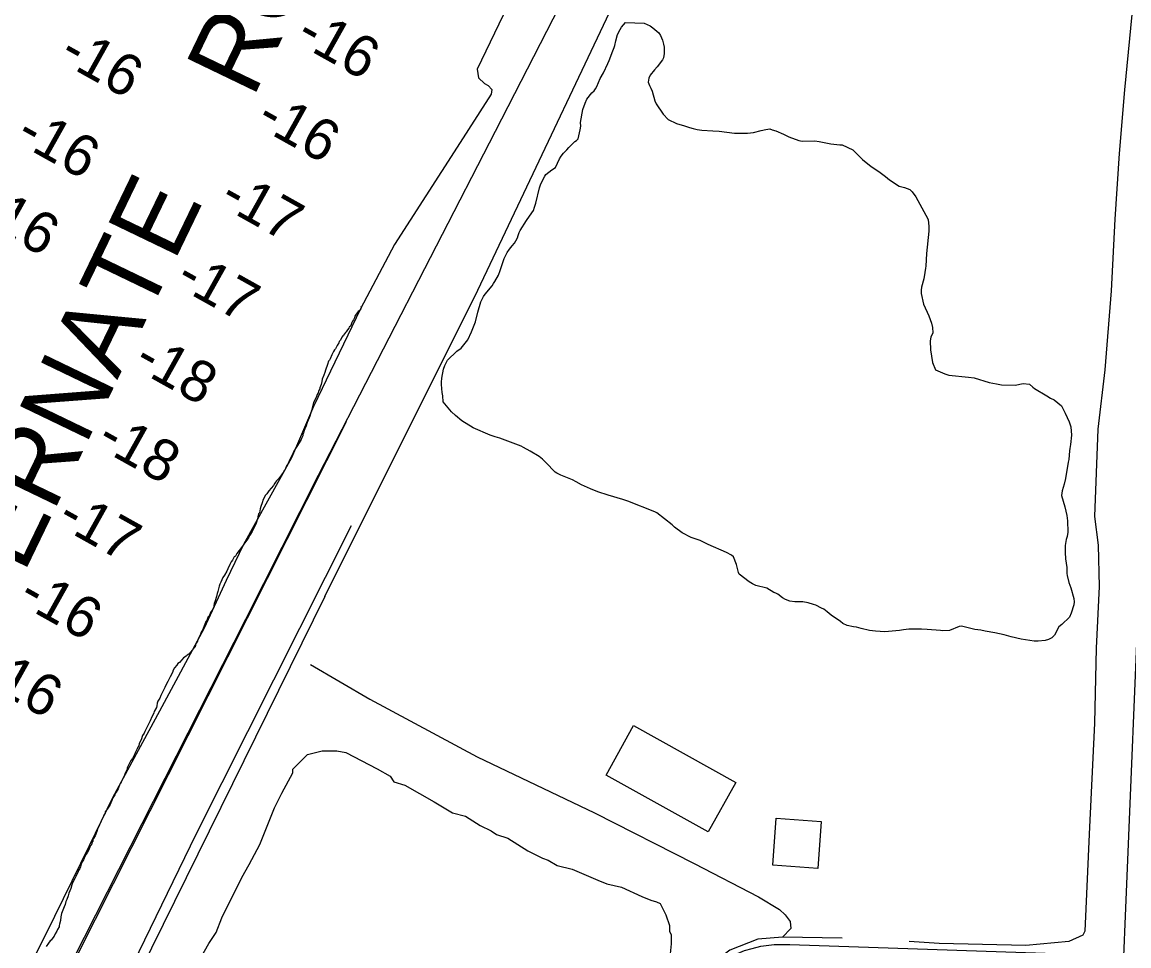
# Model space of a CAD drawing. Extents: x 3683402 to 3721514, y 487807 to 513565.
# Drawn here: x 3703895 to 3705098, y 507300 to 508305 of the extents above; entities that cross this region are included whole.
import ezdxf

# ---------------------------------------------------------------- set-up
doc = ezdxf.new("R2010")
doc.units = 0
for name, color, linetype in [('V-BLDG-OTLN', 7, 'Continuous'), ('V-LEVE-TOET', 7, 'Continuous'), ('V-RIVR-IDEN', 7, 'Continuous'), ('V-ROAD-CNTR', 7, 'Continuous'), ('V-SITE-VEGE', 7, 'Continuous'), ('V-TOPO-SHOR', 7, 'Continuous'), ('V-TOPO-SPOT', 7, 'Continuous')]:
    doc.layers.add(name, color=color, linetype=linetype)

msp = doc.modelspace()

# ---------------------------------------------------------------- linework, layer by layer
at = {"layer": 'V-BLDG-OTLN'}
for points in [[(3704670.7, 507478.2), (3704640.7, 507424.4), (3704529.6, 507486.3), (3704559.6, 507540.1)], [(3704714.4, 507439.4), (3704763.4, 507435.9), (3704759.7, 507384.6), (3704710.7, 507388.2)]]:
    msp.add_lwpolyline(points, close=True, dxfattribs=at)
at = {"layer": 'V-LEVE-TOET'}
for points in [[(3704223.9, 507680.3), (3704390.1, 508013.5), (3704576.9, 508407.5), (3704607.9, 508471.4), (3704662, 508586.2), (3704740, 508732.4), (3704803.2, 508853.8), (3704921.3, 509079.6), (3705040.6, 509320.9)], [(3704216.9, 507812.4), (3704409.6, 508186.4), (3704555.8, 508472.2), (3704578, 508525.2), (3704643.5, 508643), (3704779.8, 508906.1), (3704918.2, 509195.3), (3704970.6, 509304.3)], [(3703895.1, 507171.6), (3704054, 507487), (3704247.6, 507870.6)], [(3704223.9, 507680.3), (3703846.7, 506915.4), (3703528.7, 506294), (3703355.4, 505976.9), (3703338.6, 505959.3), (3703328.3, 505955.1), (3703313.5, 505956.1), (3703301.9, 505957.5), (3703294.3, 505960.5), (3703290.2, 505965.7), (3703290.1, 505978.7), (3703297.6, 506003.1), (3703397.2, 506210.1), (3703599.2, 506592.2), (3703887.4, 507161.4), (3704138.1, 507655.6), (3704216.9, 507812.4)], [(3703947.4, 507140.5), (3704084.3, 507421.8), (3704253, 507757.5)]]:
    msp.add_lwpolyline(points, dxfattribs=at)
at = {"layer": 'V-ROAD-CNTR'}
for points in [[(3705031.4, 505524.3), (3705055.3, 506203.7), (3705088.8, 507201.8), (3705115.9, 507856.6)], [(3703461.3, 506109.4), (3704007, 506082.8), (3704014.4, 506082.7), (3704018.5, 506082.7), (3704022, 506083.2), (3704027.1, 506085.1), (3704030.7, 506086.8), (3704033.9, 506089.4), (3704039, 506093.4), (3704044.7, 506097.7), (3704046.9, 506100), (3704050, 506103.8), (3704191.8, 506389.1), (3704638.4, 507256.7), (3704651.6, 507274.7), (3704660.9, 507285.1), (3704669.8, 507291), (3704680.1, 507295.4), (3704688.5, 507297.6), (3704697.8, 507300.3), (3704712.3, 507301.8), (3704729.2, 507301.8), (3705092.3, 507289.5)]]:
    msp.add_lwpolyline(points, dxfattribs=at)
at = {"layer": 'V-SITE-VEGE'}
for points in [[(3704584.8, 507771.4), (3704582.6, 507772.5), (3704553.3, 507784.2), (3704548, 507785.9), (3704531.9, 507790.5), (3704520.7, 507794.4), (3704512.7, 507797.5), (3704502.9, 507801.7), (3704497.1, 507805.2), (3704493, 507807.2), (3704480.5, 507812.5), (3704476.1, 507814.7), (3704474.3, 507815.8), (3704464, 507826.2), (3704460.6, 507829.7), (3704457, 507832.6), (3704447.2, 507838.6), (3704440, 507842.3), (3704437.3, 507843.8), (3704414.1, 507852.6), (3704409.2, 507853.9), (3704403.6, 507855.9), (3704385.1, 507863.8), (3704373, 507871.3), (3704366.1, 507877.3), (3704361.8, 507881.3), (3704359.8, 507883.5), (3704352.6, 507892.3), (3704352.1, 507898.6), (3704351.6, 507902.4), (3704350.9, 507910.8), (3704350.9, 507913.5), (3704351.3, 507918), (3704353, 507927.8), (3704354.4, 507931.8), (3704357.2, 507937.4), (3704367.4, 507947.2), (3704372.3, 507950.6), (3704379.4, 507959.6), (3704383.3, 507968.3), (3704387.7, 507979), (3704390.3, 507989.5), (3704393.4, 508000.9), (3704396.5, 508006.5), (3704398.2, 508009.2), (3704405.7, 508018.3), (3704407.3, 508020.8), (3704408.8, 508023), (3704412.8, 508029.7), (3704414.6, 508034.9), (3704417, 508042.7), (3704418.9, 508048.1), (3704422, 508054.5), (3704424.7, 508058.3), (3704427.5, 508061.9), (3704430.2, 508064.6), (3704431.7, 508067.3), (3704433.3, 508070.4), (3704434.2, 508072.9), (3704435, 508076.4), (3704436.1, 508078.5), (3704443, 508089.4), (3704446.5, 508094.1), (3704450.7, 508100.2), (3704452, 508104), (3704453.3, 508108.2), (3704457.2, 508124.9), (3704458.3, 508128.1), (3704461.2, 508134.1), (3704463, 508137.4), (3704464.3, 508139.5), (3704470.5, 508144.4), (3704474.7, 508147.1), (3704479.1, 508156.3), (3704480.9, 508159.4), (3704483.3, 508162.5), (3704487.1, 508166.1), (3704489.3, 508168.8), (3704495.5, 508175.1), (3704497.3, 508176.4), (3704499.3, 508178.2), (3704501.6, 508187.8), (3704502.1, 508191.8), (3704502, 508195.8), (3704504.2, 508209.9), (3704506.8, 508216.8), (3704508.8, 508221.3), (3704514.3, 508228.2), (3704516.8, 508230.5), (3704518.1, 508232.5), (3704519.4, 508235.2), (3704523.1, 508243.7), (3704526.7, 508249.9), (3704531.7, 508260), (3704532.8, 508263.3), (3704537, 508274), (3704538.5, 508277.4), (3704539.2, 508279.6), (3704540.3, 508284.8), (3704542.2, 508291.7), (3704544.9, 508297)], [(3704544.9, 508297), (3704546.4, 508299.5), (3704550.8, 508304.7), (3704571.1, 508304.1), (3704577.4, 508301), (3704580.5, 508299)], [(3704580.5, 508299), (3704587, 508293.5), (3704588.6, 508290.6), (3704590.8, 508285.3), (3704592.2, 508281.1), (3704592.7, 508277.9), (3704592.9, 508271), (3704592.1, 508266.4), (3704591, 508263.9), (3704585.2, 508256.3), (3704582.4, 508253.2), (3704577.7, 508247.3), (3704576.2, 508244.2), (3704575.3, 508239.7), (3704576.7, 508236), (3704578.2, 508233.3), (3704579.8, 508230), (3704582.6, 508219.3), (3704583.9, 508216.2), (3704591.6, 508204.9), (3704597.2, 508199.3), (3704606.3, 508194.9), (3704615, 508192.3), (3704620.4, 508190.5), (3704624.2, 508189.5), (3704628.6, 508188.4), (3704633.6, 508187.5), (3704645.6, 508186.9), (3704652.7, 508186.3), (3704669.2, 508184.4), (3704675.9, 508184.2), (3704683.5, 508184.2), (3704689.9, 508185), (3704698.2, 508187.2), (3704703.3, 508188.4), (3704707.7, 508188.9), (3704710.2, 508187.8), (3704714, 508186.9), (3704722.5, 508183.1), (3704728.3, 508180.3), (3704739, 508176.3), (3704742.6, 508175.7), (3704756.4, 508175.8), (3704761.1, 508175.1), (3704774, 508172.8), (3704783.6, 508171.7), (3704786.3, 508171.5), (3704797.9, 508166), (3704808.4, 508155.6), (3704817.6, 508147.9), (3704823.9, 508144.1), (3704827.5, 508141.7), (3704833.3, 508137), (3704837.5, 508133.5), (3704848.1, 508126.6), (3704853.9, 508125.1), (3704859.9, 508122.9), (3704862.4, 508120.5), (3704866.4, 508114.9), (3704877.2, 508095.2), (3704879.5, 508090.3), (3704880.4, 508082.9), (3704880.4, 508077.6), (3704877.9, 508053.5), (3704877.1, 508039.7), (3704876.9, 508037.5), (3704876, 508032.8), (3704875, 508025.9), (3704872.6, 508016.7), (3704872.1, 508013.6), (3704872.2, 508009.8), (3704874.7, 507998.5), (3704880.3, 507985.8), (3704883.3, 507977.6), (3704884.4, 507973.1), (3704884.7, 507967.3), (3704882.5, 507962.6), (3704881.8, 507958.6), (3704882.3, 507948.6), (3704884.4, 507934.8), (3704887.6, 507927), (3704897.9, 507922.4), (3704902.1, 507921.3), (3704923.5, 507919), (3704929.8, 507918.1), (3704945.8, 507913.3), (3704953.9, 507911.6), (3704959.4, 507910.7), (3704974.1, 507910.4), (3704982.8, 507912.2), (3704989.7, 507911.4), (3704993.5, 507908.1), (3704995.3, 507906.7), (3705008.8, 507898.8), (3705012.6, 507896.1), (3705016.6, 507894.2), (3705024.4, 507887.7), (3705028.7, 507879.7), (3705033, 507870.4), (3705034.6, 507864.9), (3705035.3, 507855.9)], [(3705035.3, 507855.9), (3705034.5, 507845.9), (3705033.8, 507841.2), (3705033.4, 507839), (3705032.4, 507829.4), (3705031.7, 507826.5), (3705028.9, 507808.7), (3705027.6, 507802.6), (3705025.4, 507795.5), (3705024.8, 507792.8), (3705024.6, 507790.2), (3705028.2, 507778.1), (3705030.3, 507768.6), (3705031.2, 507762.6), (3705031.5, 507750.5), (3705030.6, 507745.6), (3705029.8, 507742.5), (3705028.7, 507735.8), (3705028.7, 507728.2), (3705029, 507721.5), (3705030.2, 507711.8), (3705030.4, 507705.5), (3705030.7, 507703.1), (3705032.7, 507695.5), (3705033.6, 507692.6), (3705034.8, 507689.7), (3705038, 507678.4), (3705038.4, 507674.8), (3705038, 507671.5), (3705035.2, 507662.3), (3705033.4, 507658.1), (3705025, 507650), (3705021.6, 507647.3), (3705017, 507638.4), (3705013.9, 507635.4), (3705010.4, 507633.6), (3705006.8, 507632.7), (3704999.2, 507631.8), (3704994.8, 507632), (3704980.7, 507634.1), (3704970, 507636.7), (3704962.2, 507638.9), (3704952.2, 507640.9), (3704941.5, 507642.6), (3704937, 507643.7), (3704930.5, 507644.5), (3704916, 507648), (3704913.4, 507647.8), (3704902.9, 507643.5), (3704895.6, 507643), (3704892.9, 507643.4), (3704878.6, 507644.7), (3704872.4, 507644.8), (3704858.6, 507645), (3704853, 507644.3), (3704848.5, 507643.6), (3704832.5, 507641.9), (3704822.5, 507642.8), (3704815.8, 507643.6), (3704806.9, 507645.6), (3704801.7, 507646.9), (3704798.6, 507647.3), (3704791.5, 507649), (3704787, 507651.2), (3704784.3, 507653.2), (3704774.2, 507660.1), (3704770, 507663.8), (3704766.2, 507666.5), (3704763.9, 507667.8), (3704757.5, 507670.9), (3704755.2, 507671.8), (3704749.4, 507673.5), (3704743.6, 507674.6), (3704741.2, 507674.8), (3704739, 507674.6), (3704734.9, 507674.5), (3704729.4, 507675.2), (3704724.7, 507677.1), (3704721.5, 507678.9), (3704716.2, 507683.1), (3704714.2, 507684.2), (3704712.1, 507684.6), (3704704.5, 507689.5), (3704692.3, 507692.5), (3704688.9, 507694.1), (3704685.1, 507696.5), (3704674.4, 507704.7), (3704673.5, 507706.7), (3704672.3, 507710.9), (3704671.4, 507715.1), (3704668, 507723.4), (3704665.8, 507725.4), (3704660.4, 507728.4), (3704640.5, 507736.8), (3704631.8, 507741.2), (3704624.2, 507743.8), (3704622.2, 507744.7), (3704612.2, 507749.8), (3704603.9, 507755.9), (3704601.4, 507758.2), (3704584.8, 507771.4)], [(3704090.1, 507288.9), (3704098, 507302.9), (3704106, 507314.9), (3704111.9, 507330.9), (3704133.7, 507374.8), (3704141.6, 507388.8), (3704153.5, 507410.8), (3704169.3, 507450.7), (3704177.2, 507466.7), (3704189.1, 507488.6), (3704189.1, 507492.6), (3704205, 507508.6), (3704221, 507512.7), (3704236.9, 507512.7), (3704246.9, 507510.8), (3704280.9, 507492.9), (3704294.8, 507485), (3704298.8, 507479), (3704310.8, 507475.1), (3704342.8, 507457.2), (3704362.8, 507445.3), (3704376.7, 507441.4), (3704392.7, 507431.5), (3704404.7, 507425.5), (3704410.7, 507421.6), (3704422.7, 507417.6), (3704444.7, 507403.7), (3704460.6, 507395.8), (3704466.6, 507393.8), (3704476.6, 507387.9), (3704492.6, 507384), (3704520.5, 507372.1), (3704530.5, 507368.1), (3704546.5, 507364.2), (3704568.4, 507354.3), (3704578.4, 507350.3), (3704584.4, 507348.4), (3704588.4, 507346.4), (3704594.4, 507334.4), (3704598.5, 507322.5), (3704598.5, 507316.5), (3704600.5, 507312.5), (3704600.5, 507302.6), (3704598.6, 507284.6)]]:
    msp.add_lwpolyline(points, dxfattribs=at)
at = {"layer": 'V-TOPO-SHOR'}
for points in [[(3704498.3, 508480), (3704389.7, 508253.9), (3704390.9, 508244.5), (3704397.6, 508238.4), (3704401.5, 508236), (3704405.3, 508231.9), (3704404.6, 508226.7), (3704367.9, 508169.1), (3704299.7, 508063.4), (3704262.7, 507993.4), (3704211.7, 507887.2), (3704187.7, 507831.2), (3704135.6, 507737), (3704116.8, 507697.7), (3704092.9, 507645.9), (3704044.2, 507555.8), (3703993.1, 507461.6), (3703967.8, 507409.4), (3703930.2, 507332.5), (3703904, 507279.9), (3703872.7, 507213.9), (3703839.3, 507144.2)], [(3705107.4, 508420.6), (3705100.9, 508313.4), (3705092.9, 508231.4), (3705087.1, 508162.3), (3705082.6, 508090.9), (3705078.4, 508012.9), (3705071.6, 507927.1), (3705064.1, 507862.3), (3705060.3, 507767.6), (3705064.5, 507736.3), (3705065.5, 507691.2), (3705062.1, 507624.4), (3705060.5, 507542.6), (3705054.6, 507422), (3705050, 507316.6), (3705047.6, 507312), (3705032.5, 507305.1), (3704985.9, 507300.9), (3704891.6, 507303.2), (3704859.1, 507305.1)], [(3704263.2, 507996.3), (3704263.6, 507995.1), (3704263.1, 507993.1), (3704261.9, 507991.8), (3704261.1, 507991), (3704260.3, 507990.2), (3704259.1, 507989), (3704257.9, 507987.4), (3704257.4, 507986.2), (3704256.6, 507985.4), (3704256.2, 507983.3), (3704255, 507981.3), (3704254.2, 507979.7), (3704253.4, 507978.5), (3704252.5, 507976.4), (3704251.7, 507974.4), (3704250.5, 507973.6), (3704250.1, 507972.4), (3704248.5, 507970.4), (3704247.2, 507968.3), (3704246.4, 507967.5), (3704244.4, 507964.7), (3704243.6, 507963.9), (3704242.8, 507962.7), (3704240.7, 507959), (3704239.5, 507957.8), (3704239.1, 507956.2), (3704237.4, 507953.3), (3704235.4, 507949.7), (3704234.6, 507948.5), (3704233.4, 507946.9), (3704231.7, 507943.2), (3704229.7, 507938.8), (3704228.9, 507937.5), (3704228.1, 507936.3), (3704226.8, 507932.7), (3704224.8, 507926.6), (3704224, 507924.2), (3704222.7, 507921.3), (3704221.1, 507916.9), (3704220.7, 507914.4), (3704219.9, 507910.8), (3704218.6, 507907.5), (3704218.6, 507906.3), (3704217.8, 507905.1), (3704217, 507903.5), (3704216.6, 507901.8), (3704215.8, 507900.2), (3704214.9, 507897.8), (3704213.7, 507895.4), (3704211.7, 507891.3), (3704210.4, 507887.2), (3704209.6, 507882.8), (3704207.6, 507876.7), (3704206.8, 507874.7), (3704204.7, 507869.8), (3704203.9, 507867.4), (3704203.5, 507865.7), (3704202.3, 507862.9), (3704201.4, 507860.9), (3704200.6, 507858.4), (3704200.2, 507857.2), (3704200.2, 507855.2), (3704198.6, 507852.4), (3704198.2, 507851.1), (3704196.1, 507847.5), (3704193.7, 507843.4), (3704192, 507841.4), (3704190.4, 507838.6), (3704189.6, 507836.6), (3704188, 507833.7), (3704186.7, 507830.9), (3704184.7, 507826.8), (3704183.5, 507824), (3704182.2, 507822.4), (3704181, 507818.7), (3704179.8, 507817.5), (3704178.6, 507815.1), (3704174.9, 507810.2), (3704173.3, 507808.2), (3704171.6, 507806.2), (3704170.4, 507804.9), (3704168.8, 507802.5), (3704168, 507801.3), (3704165.5, 507798.1), (3704163.1, 507795.2), (3704162.3, 507794.4), (3704161, 507792), (3704159.4, 507790.8), (3704156.9, 507785.9), (3704155.7, 507782.2), (3704154.5, 507778.2), (3704153.7, 507775.8), (3704152.8, 507771.3), (3704152, 507770.5), (3704151.2, 507767.2), (3704150.8, 507764.8), (3704149.2, 507760.3), (3704148.3, 507757.5), (3704145.1, 507751), (3704142.6, 507747)], [(3704142.6, 507747), (3704141.4, 507744.9), (3704139.8, 507742.9), (3704138.1, 507740.1), (3704136.5, 507738.5), (3704134.5, 507735.2), (3704128.3, 507727.1), (3704126.7, 507724.3), (3704125.5, 507723.5), (3704123.5, 507719.8), (3704122.2, 507718.2), (3704120.6, 507715.4), (3704118.6, 507710.5), (3704117.3, 507708.1), (3704114.9, 507703.6), (3704113.2, 507701.2), (3704110.8, 507695.9), (3704110, 507693.9), (3704109.2, 507691.8), (3704107.5, 507685.8), (3704107.1, 507683.7), (3704106.3, 507680.5), (3704104.6, 507675.6), (3704103.8, 507672.8), (3704103.4, 507670.3), (3704103.4, 507668.7), (3704102.2, 507667.1), (3704101.4, 507665.5), (3704099.7, 507663), (3704098.5, 507660.2), (3704098.1, 507659), (3704097.3, 507658.2), (3704096.5, 507656.6), (3704095.6, 507654.5), (3704094.8, 507653.3), (3704094.4, 507652.1), (3704092.8, 507648.4), (3704091.6, 507645.6), (3704090.3, 507642.8), (3704089.5, 507641.6), (3704088.7, 507639.5), (3704087.5, 507636.7), (3704085.8, 507633.4), (3704085.4, 507631.8), (3704084.2, 507629.8), (3704083.4, 507628.6), (3704083.4, 507627.4), (3704083, 507625.7), (3704080.1, 507622.5), (3704076, 507617.6), (3704074.4, 507616.8), (3704073.2, 507615.6), (3704070.3, 507613.6), (3704068.7, 507611.6), (3704065.9, 507608.7), (3704064.2, 507607.5), (3704063, 507605.9), (3704060.6, 507602.7), (3704059.3, 507600.2), (3704058.5, 507597.8), (3704055.7, 507592.9), (3704053.2, 507588.1), (3704050.8, 507583.2), (3704049.9, 507581.6), (3704047.5, 507576.3), (3704045.9, 507572.7), (3704044.6, 507569.8), (3704042.6, 507566.6), (3704041.8, 507564.5), (3704041.4, 507561.7), (3704040.9, 507559.7), (3704038.5, 507555.2), (3704038.1, 507554), (3704037.3, 507552), (3704036, 507549.5), (3704034, 507545.1), (3704033.2, 507543.1), (3704032, 507541), (3704028.3, 507533.7), (3704027.5, 507531.7), (3704025.8, 507529.3), (3704024.2, 507524.4), (3704022.1, 507520.4), (3704021.7, 507517.9), (3704020.9, 507516.7), (3704020.1, 507514.7), (3704018.1, 507511), (3704017.6, 507509.4), (3704014.8, 507504.1), (3704013.2, 507502.1), (3704010.3, 507496.4), (3704009.1, 507494), (3704009.1, 507492.8), (3704008.3, 507491.2), (3704007, 507488.3), (3704006.2, 507486.3), (3704003.3, 507480.2), (3704002.1, 507477.4), (3704001.3, 507476.2), (3703999.3, 507471.3), (3703997.2, 507467.6)], [(3704208.3, 507606.4), (3704272.7, 507568.7), (3704389.4, 507506.2), (3704517.2, 507445.2), (3704625.2, 507389.9), (3704695.3, 507353.8), (3704718.1, 507340.1), (3704724.4, 507334.4), (3704729.8, 507326.8), (3704730.5, 507319.3), (3704721.2, 507309.8)], [(3703997.2, 507467.6), (3703995.6, 507464.8), (3703993.5, 507461.6), (3703992.3, 507458.7), (3703991.5, 507455.9), (3703989.5, 507451.8), (3703988.6, 507450.6), (3703985.4, 507446.2), (3703985.4, 507444.9), (3703983.7, 507442.5), (3703982.9, 507440.5), (3703980.9, 507436), (3703977.6, 507428.7), (3703976.8, 507427.5), (3703976.4, 507425.9), (3703976, 507424.7), (3703974.3, 507420.2), (3703972.7, 507417.4), (3703971.9, 507415.7), (3703971.9, 507414.1), (3703971.1, 507413.3), (3703970.7, 507412.1), (3703970.2, 507410.5), (3703969, 507408.9), (3703967.4, 507404.8), (3703966.2, 507402.4), (3703964.5, 507400.3), (3703962.5, 507395.9), (3703961.7, 507393.9), (3703960.4, 507391.8), (3703959.2, 507389.4), (3703958.4, 507386.6), (3703957.6, 507384.5), (3703956.4, 507382.5), (3703955.5, 507380.1), (3703953.9, 507377.6), (3703953.5, 507376), (3703952.3, 507373.6), (3703949.8, 507369.1), (3703949, 507366.7), (3703947.8, 507363), (3703945.7, 507357.8), (3703944.9, 507354.9), (3703943.7, 507350.9), (3703942.4, 507348.8), (3703941.6, 507345.6), (3703940.8, 507342.8), (3703937.9, 507335.5), (3703937.5, 507333.8), (3703937.1, 507332.2), (3703936.7, 507328.1), (3703935.5, 507324.1), (3703935.1, 507322.5), (3703935.1, 507321.3), (3703933.4, 507318.4), (3703932.6, 507316.4), (3703931, 507313.5), (3703929.7, 507311.1), (3703927.3, 507307.9), (3703926.5, 507306.7), (3703925.3, 507305.9), (3703923.6, 507303.4), (3703921.2, 507299.8)], [(3704786.3, 507308.7), (3704721.2, 507309.8), (3704694.7, 507307.8), (3704664.1, 507295.7), (3704644.1, 507280.5), (3704623.4, 507256.9), (3704597.2, 507205.2), (3704582.4, 507176.4), (3704564.8, 507135.8)]]:
    msp.add_lwpolyline(points, dxfattribs=at)

# ---------------------------------------------------------------- texts
at = {"layer": 'V-RIVR-IDEN'}
msp.add_text('(ALTERNATE    ROUTE)', height=83, rotation=64.2693, dxfattribs=at).set_placement((3703792.2, 507487.7))
at = {"layer": 'V-TOPO-SPOT'}
for s, p in [('-16', (3704190.4, 508283.6)), ('-16', (3703933.2, 508263.5)), ('-16', (3704147.3, 508192.9)), ('-16', (3703886.1, 508175.5)), ('-17', (3704107.4, 508106.6)), ('-16', (3703842.2, 508091.7)), ('-17', (3704059.6, 508019.1)), ('-18', (3704014.2, 507929.6)), ('-18', (3703973.8, 507844)), ('-17', (3703930.8, 507758.7)), ('-16', (3703888.7, 507673.7)), ('-16', (3703845.8, 507589.2))]:
    msp.add_text(s, height=45, rotation=330.7933, dxfattribs=at).set_placement(p)

doc.saveas('drawing.dxf')
